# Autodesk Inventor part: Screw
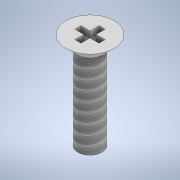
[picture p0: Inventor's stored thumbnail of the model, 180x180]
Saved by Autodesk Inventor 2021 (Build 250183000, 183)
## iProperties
Created: 2021-02
Part Number: Screw
Material: Generic
Document SubType Name: Modeling
Designer: callu
Density: 1 g/cm^3
Appearance: Default
Author: callu
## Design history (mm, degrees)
sketch "Sketch1"
  geometry: C1 r 1 at (0, 0); 1 further point
  constraints: 1 centre point, 1 coincident
  dimensions: "d0" = 2 diameter of C1
workplane "Work Plane1"
sketch "Sketch2"
  geometry: C1 r 2 at (0, 0); 1 further point
  constraints: 1 centre point, 1 coincident
  dimensions: "d2" = 4 diameter of C1
extrude "Extrusion1" new body sketch "Sketch1" distance "d3" = 7; taper "d4" = 0 deg
loft "Loft1" dims "d5" = 0, "d6" = 90 deg, "d7" = 0, "d8" = 90 deg
  node "Edges1"
sketch "Sketch3"
  geometry: L1 (-1, 0.25)-(-1, -0.25); L2 (1, -0.25)-(1, 0.25); L3 (0.25, 1)-(-0.25, 1); L4 (-0.25, -1)-(0.25, -1); L5 (1, 0.25)-(0.25, 0.25); L6 (-0.25, 0.25)-(-1, 0.25); L7 (-1, -0.25)-(-0.25, -0.25); L8 (0.25, -0.25)-(1, -0.25); L9 (-0.25, 1)-(-0.25, 0.25); L10 (-0.25, -0.25)-(-0.25, -1); L11 (0.25, -1)-(0.25, -0.25); L12 (0.25, 0.25)-(0.25, 1); 1 further point
  constraints: 24 end point, 10 parallel, 4 perpendicular, 3 horizontal
  dimensions: "d9" = 2 distance of L2.start L1.end; "d10" = 0.5 distance of L2.start L2.end; "d12" = 1 distance from line of point (0, 0) L2; "d13" = 0.5 distance of L4.end L4.start; "d14" = 2 distance of L4.start L3.end; "d16" = 1 distance from line of L3 point (0, 0)
extrude "Extrusion2" cut sketch "Sketch3" distance "d17" = 0.5; taper "d18" = 0 deg
thread "Thread1" dims "d19" = 50, "d20" = 0
body "Solid1"
other parameters: "d1" = 1, "d11" = 0.25, "d15" = 0.25
